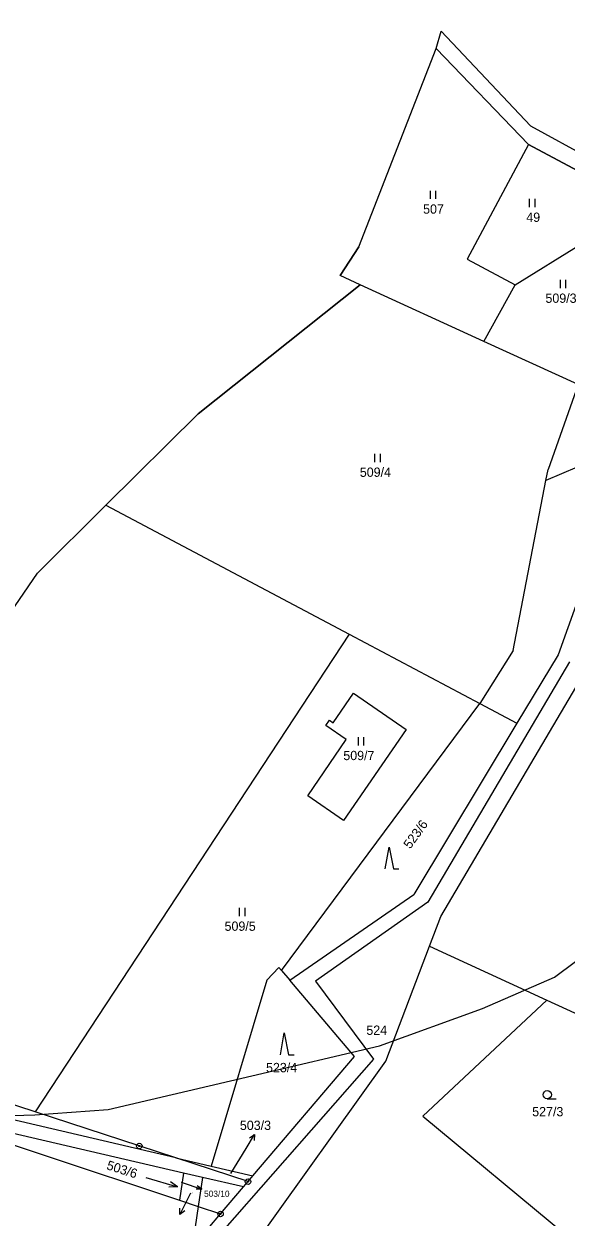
# Model space of a CAD drawing. Extents: x -546762 to -540209, y -1046851 to -1035694.
# Drawn here: x -544699.3 to -544600.2, y -1042892.1 to -1042674 of the extents above; entities that cross this region are included whole.
import ezdxf

# ---------------------------------------------------------------- set-up
doc = ezdxf.new("R2010")
doc.units = 0
for name, color, linetype in [('Vrstva 1', 7, 'Continuous'), ('Vrstva 16', 7, 'Continuous'), ('Vrstva 18', 7, 'Continuous'), ('Vrstva 24', 7, 'Continuous'), ('Vrstva 25', 7, 'Continuous'), ('Vrstva 52', 7, 'Continuous'), ('Vrstva 6', 7, 'Continuous')]:
    doc.layers.add(name, color=color, linetype=linetype)

msp = doc.modelspace()

# ---------------------------------------------------------------- linework, layer by layer
at = {"layer": 'Vrstva 1'}
for p, q in [((-544582.72, -1042748.28), (-544603.93, -1042757.45)), ((-544603.93, -1042757.45), (-544603.54, -1042755.4)), ((-544609.88, -1042788.51), (-544603.93, -1042757.45)), ((-544670.17, -1042884.04), (-544721.48, -1042872.17)), ((-544670.17, -1042884.04), (-544670.9, -1042889.02)), ((-544666.71, -1042884.84), (-544670.17, -1042884.04)), ((-544670.9, -1042889.02), (-544667.49, -1042890.16))]:
    msp.add_line(p, q, dxfattribs=at)
for points in [[(-544623.97, -1042678.49), (-544623.09, -1042675.28)], [(-544606.76, -1042692.62), (-544623.09, -1042675.28)], [(-544638.13, -1042714.75), (-544623.97, -1042678.49)], [(-544607.13, -1042696.02), (-544623.97, -1042678.49)], [(-544606.76, -1042692.62), (-544595.83, -1042698.58)], [(-544598.1, -1042700.83), (-544607.13, -1042696.02)], [(-544638.13, -1042714.75), (-544641.52, -1042719.99)], [(-544637.87, -1042721.66), (-544641.52, -1042719.99)], [(-544637.87, -1042721.66), (-544667.45, -1042745.24)], [(-544598.03, -1042739.89), (-544603.54, -1042755.4)], [(-544667.45, -1042745.24), (-544684.33, -1042761.97)], [(-544684.33, -1042761.97), (-544696.84, -1042774.37)], [(-544728.08, -1042820), (-544696.84, -1042774.37)], [(-544596.37, -1042774.48), (-544601.69, -1042789.3)], [(-544609.88, -1042788.51), (-544616.02, -1042798.19)], [(-544599.59, -1042790.6), (-544625.53, -1042834.55)], [(-544601.69, -1042789.3), (-544609.22, -1042801.8)], [(-544623.1, -1042837.12), (-544597.05, -1042792.89)], [(-544652.22, -1042847.04), (-544616.02, -1042798.19)], [(-544616.02, -1042798.19), (-544609.22, -1042801.8)], [(-544609.22, -1042801.8), (-544628.09, -1042833.14)], [(-544650.75, -1042848.77), (-544628.09, -1042833.14)], [(-544625.53, -1042834.55), (-544646.02, -1042848.97)], [(-544625.17, -1042842.54), (-544623.1, -1042837.12)], [(-544633.2, -1042863.62), (-544625.17, -1042842.54)], [(-544625.17, -1042842.54), (-544603.74, -1042852.41)], [(-544654.94, -1042848.8), (-544652.72, -1042846.45)], [(-544652.22, -1042847.04), (-544652.72, -1042846.45)], [(-544654.94, -1042848.8), (-544665.1, -1042882.8)], [(-544638.89, -1042862.72), (-544650.75, -1042848.77)], [(-544646.02, -1042848.97), (-544635.42, -1042863.24)], [(-544626.41, -1042873.63), (-544603.74, -1042852.41)], [(-544603.74, -1042852.41), (-544595.11, -1042856.39)], [(-544697.28, -1042872.86), (-544739.39, -1042859.06)], [(-544657.48, -1042884.58), (-544638.89, -1042862.72)], [(-544635.42, -1042863.24), (-544663, -1042894.65)], [(-544657.26, -1042897.22), (-544633.2, -1042863.62)], [(-544721.48, -1042872.17), (-544670.9, -1042889.02)], [(-544678.23, -1042879.1), (-544697.28, -1042872.86)], [(-544626.41, -1042873.63), (-544600.3, -1042895.33)], [(-544671.58, -1042881.28), (-544678.23, -1042879.1)], [(-544658.36, -1042885.61), (-544671.58, -1042881.28)], [(-544671.58, -1042881.28), (-544665.1, -1042882.8)], [(-544665.1, -1042882.8), (-544657.48, -1042884.58)], [(-544658.36, -1042885.61), (-544657.48, -1042884.58)], [(-544666.71, -1042884.84), (-544667.49, -1042890.16)], [(-544663.39, -1042891.53), (-544659.18, -1042886.58)], [(-544659.18, -1042886.58), (-544658.36, -1042885.61)], [(-544667.49, -1042890.16), (-544674.76, -1042939.8)], [(-544667.49, -1042890.16), (-544663.39, -1042891.53)], [(-544665.66, -1042894.2), (-544663.39, -1042891.53)]]:
    msp.add_lwpolyline(points, dxfattribs=at)
at = {"layer": 'Vrstva 16'}
for p, q in [((-544658.73, -1042879.55), (-544657.17, -1042876.99)), ((-544669.47, -1042888.92), (-544670.83, -1042891.6))]:
    msp.add_line(p, q, dxfattribs=at)
for points in [[(-544658.11, -1042877.58), (-544657.17, -1042876.99), (-544657.26, -1042878.1)], [(-544661.53, -1042884.13), (-544658.73, -1042879.55)], [(-544668.88, -1042887.75), (-544669.47, -1042888.92)], [(-544669.93, -1042890.93), (-544670.83, -1042891.6), (-544670.82, -1042890.48)]]:
    msp.add_lwpolyline(points, dxfattribs=at)
at = {"layer": 'Vrstva 24'}
for centre, radius in [((-544678.23, -1042879.1), 0.5), ((-544678.23, -1042879.1), 0.1), ((-544658.36, -1042885.61), 0.5), ((-544658.36, -1042885.61), 0.1), ((-544663.39, -1042891.53), 0.5), ((-544663.39, -1042891.53), 0.1)]:
    msp.add_circle(centre, radius, dxfattribs=at)
at = {"layer": 'Vrstva 25'}
for p, q in [((-544625.03, -1042705.96), (-544625.03, -1042704.46)), ((-544624.03, -1042705.96), (-544624.03, -1042704.46)), ((-544606.91, -1042707.46), (-544606.91, -1042705.96)), ((-544605.91, -1042707.46), (-544605.91, -1042705.96)), ((-544601.26, -1042722.26), (-544601.26, -1042720.76)), ((-544600.26, -1042722.26), (-544600.26, -1042720.76)), ((-544635.18, -1042754.07), (-544635.18, -1042752.57)), ((-544634.18, -1042754.07), (-544634.18, -1042752.57)), ((-544638.2, -1042805.86), (-544638.2, -1042804.36)), ((-544637.2, -1042805.86), (-544637.2, -1042804.36)), ((-544659.9, -1042837.06), (-544659.9, -1042835.56)), ((-544658.9, -1042837.06), (-544658.9, -1042835.56)), ((-544603.68, -1042870.47), (-544602.08, -1042870.47))]:
    msp.add_line(p, q, dxfattribs=at)
for points in [[(-544633.28, -1042828.46), (-544632.58, -1042824.46), (-544631.78, -1042828.46), (-544630.78, -1042828.46)], [(-544652.44, -1042862.41), (-544651.74, -1042858.41), (-544650.94, -1042862.41), (-544649.94, -1042862.41)], [(-544677.01, -1042884.86), (-544671.25, -1042886.54), (-544672.55, -1042885.64)], [(-544671.25, -1042886.54), (-544672.83, -1042886.6)], [(-544670.6, -1042885.72), (-544666.78, -1042887), (-544667.63, -1042886.36)], [(-544666.78, -1042887), (-544667.84, -1042887)]]:
    msp.add_lwpolyline(points, dxfattribs=at)
msp.add_circle((-544603.68, -1042869.72), 0.75, dxfattribs=at)
at = {"layer": 'Vrstva 52'}
for points in [[(-544749.41, -1042812.98), (-544728.08, -1042820), (-544696.84, -1042774.37), (-544684.33, -1042761.97), (-544667.45, -1042745.24), (-544637.87, -1042721.66), (-544641.52, -1042719.99), (-544638.13, -1042714.75), (-544623.97, -1042678.49), (-544607.13, -1042696.02), (-544598.1, -1042700.83), (-544587.56, -1042710.42), (-544566.83, -1042729.28), (-544565.67, -1042726.67), (-544561, -1042716.16), (-544566.52, -1042697.26), (-544567.8, -1042689.76), (-544554.69, -1042683.54), (-544543.88, -1042688.11), (-544522.03, -1042685.62), (-544507.06, -1042669.9), (-544495.63, -1042640.4), (-544502.76, -1042623.84), (-544501.01, -1042619.24)], [(-544749.41, -1042812.98), (-544754.57, -1042818.67), (-544763.05, -1042828.63), (-544771.74, -1042839.24), (-544791.66, -1042865.11), (-544756.05, -1042871.05), (-544731.89, -1042873.17), (-544711.55, -1042873.8), (-544697.35, -1042873.38), (-544683.94, -1042872.42), (-544657.66, -1042866.27), (-544634.35, -1042860.76), (-544615.49, -1042853.98), (-544602.35, -1042848.25), (-544591.33, -1042839.98), (-544566.3, -1042815.86)]]:
    msp.add_lwpolyline(points, dxfattribs=at)
at = {"layer": 'Vrstva 6'}
for points in [[(-544607.13, -1042696.02), (-544618.3, -1042716.99)], [(-544609.57, -1042721.64), (-544597.52, -1042714.25)], [(-544618.3, -1042716.99), (-544609.57, -1042721.64)], [(-544615.28, -1042732), (-544637.87, -1042721.66)], [(-544615.28, -1042732), (-544609.57, -1042721.64)], [(-544598.03, -1042739.89), (-544615.28, -1042732)], [(-544684.33, -1042761.97), (-544639.89, -1042785.53)], [(-544639.89, -1042785.53), (-544697.28, -1042872.86)], [(-544639.89, -1042785.53), (-544616.02, -1042798.19)], [(-544642.82, -1042801.72), (-544639.11, -1042796.32)], [(-544639.11, -1042796.32), (-544629.47, -1042802.95)], [(-544644.15, -1042802.23), (-544643.48, -1042801.26)], [(-544643.48, -1042801.26), (-544642.82, -1042801.72)], [(-544640.4, -1042804.81), (-544644.15, -1042802.23)], [(-544629.47, -1042802.95), (-544640.9, -1042819.58)], [(-544647.46, -1042815.07), (-544640.4, -1042804.81)], [(-544640.9, -1042819.58), (-544647.46, -1042815.07)], [(-544652.22, -1042847.04), (-544650.75, -1042848.77)], [(-544671.58, -1042881.28), (-544725.52, -1042868.66)], [(-544659.18, -1042886.58), (-544666.71, -1042884.84)]]:
    msp.add_lwpolyline(points, dxfattribs=at)

# ---------------------------------------------------------------- texts
at = {"layer": 'Vrstva 16'}
msp.add_text('503/3', height=1.7, dxfattribs=at).set_placement((-544659.85, -1042876.17))
at = {"layer": 'Vrstva 18'}
for s, height, p in [('507', 1.7, (-544626.37, -1042708.66)), ('49', 1.7, (-544607.51, -1042710.16)), ('509/3', 1.7, (-544604.01, -1042724.96)), ('509/4', 1.7, (-544637.93, -1042756.77)), ('509/7', 1.7, (-544640.95, -1042808.56)), ('509/5', 1.7, (-544662.65, -1042839.76)), ('524', 1.7, (-544636.74, -1042858.78)), ('523/4', 1.7, (-544655.07, -1042865.61)), ('527/3', 1.7, (-544606.43, -1042873.67)), ('503/3', 0.1, (-544661.72, -1042884.13)), ('503/11', 0.1, (-544668.88, -1042887.75)), ('503/10', 1.14, (-544666.4, -1042888.4))]:
    msp.add_text(s, height=height, dxfattribs=at).set_placement(p)
for s, rotation, p in [('523/6', 54.037, (-544628.73, -1042824.9)), ('503/6', 342.3291, (-544684.34, -1042883.32))]:
    msp.add_text(s, height=1.7, rotation=rotation, dxfattribs=at).set_placement(p)

doc.saveas('drawing.dxf')
